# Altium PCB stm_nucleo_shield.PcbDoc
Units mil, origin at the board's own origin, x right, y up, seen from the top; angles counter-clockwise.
Board outline 4500 x 5500 mil, 2 copper layers (Top Layer, Bottom Layer); 14 components, 82 nets, 154 pads, 2 vias.
Unrouted connection lines stored in the file: 26.
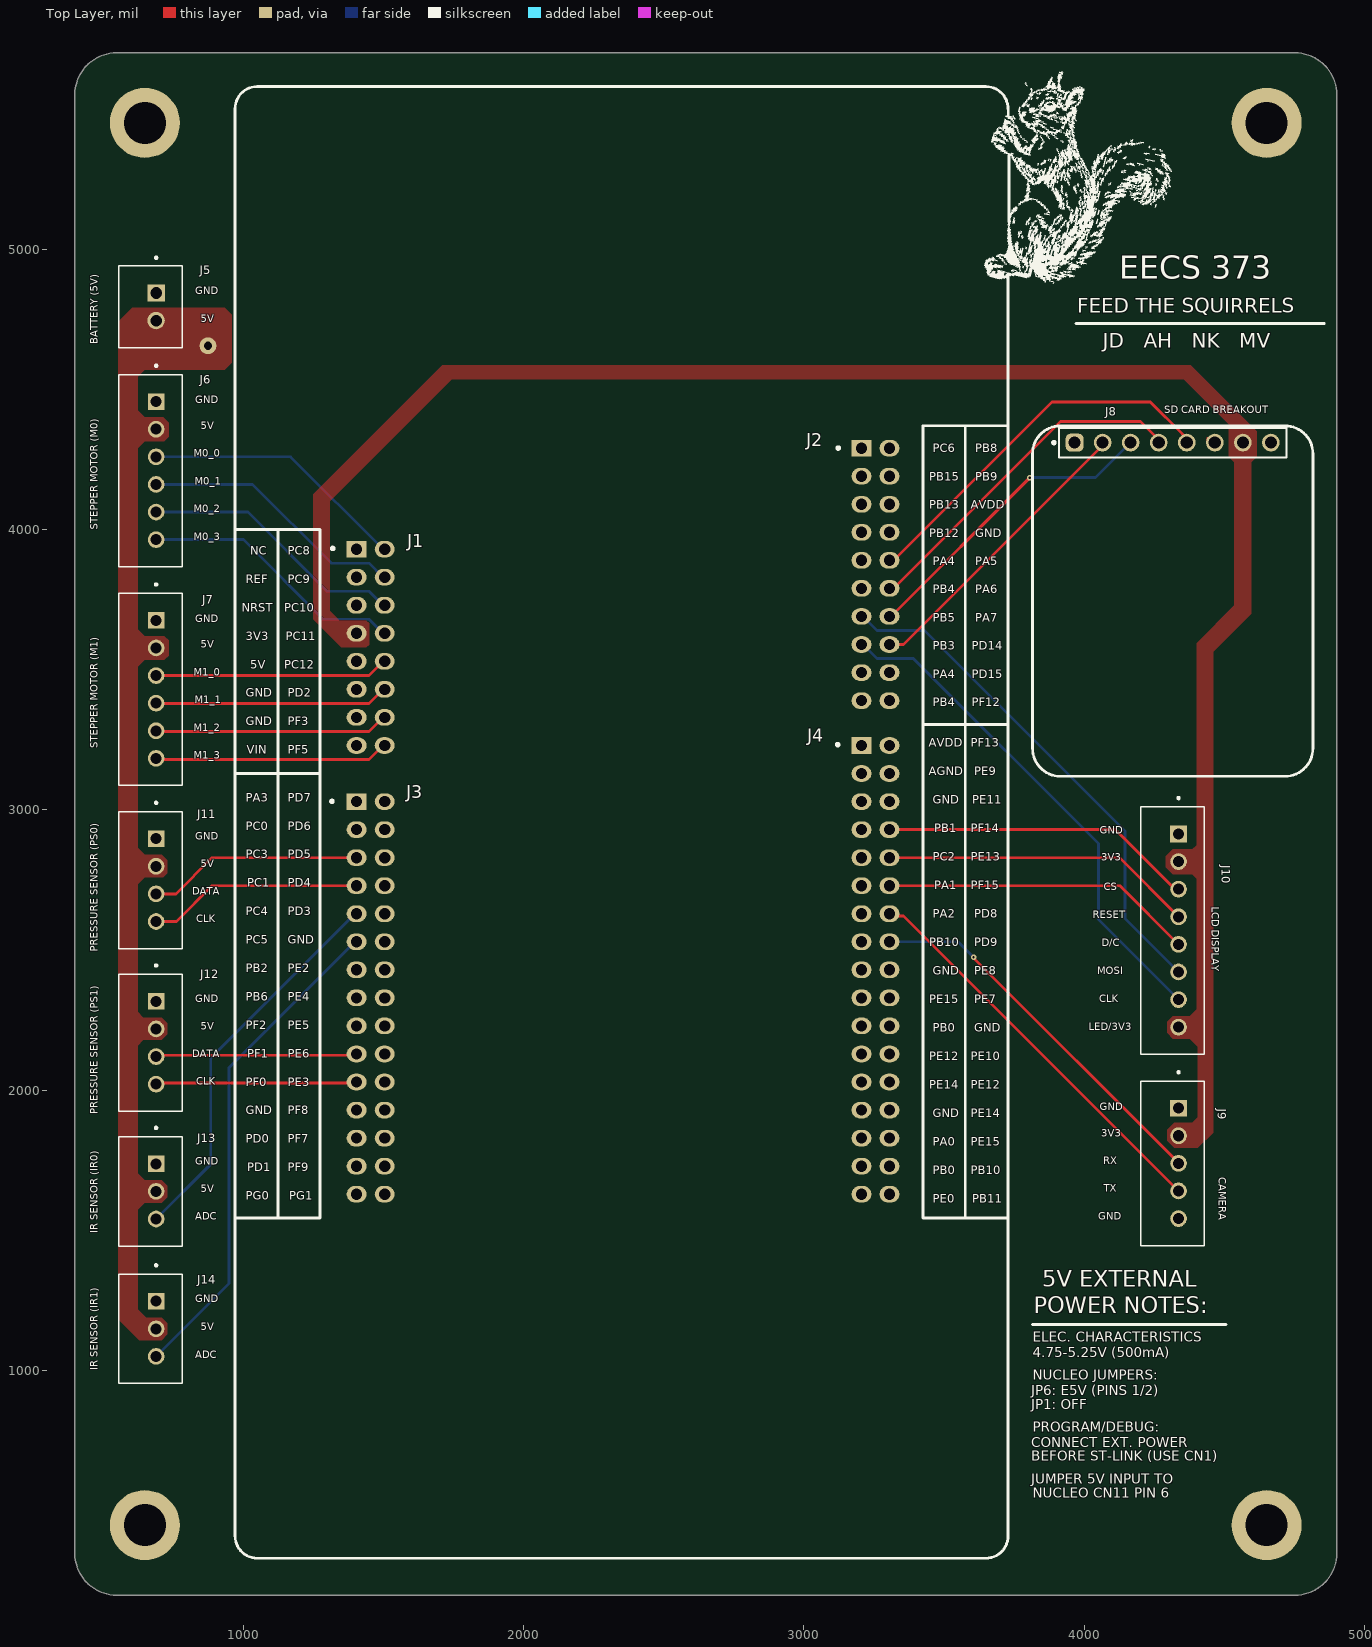
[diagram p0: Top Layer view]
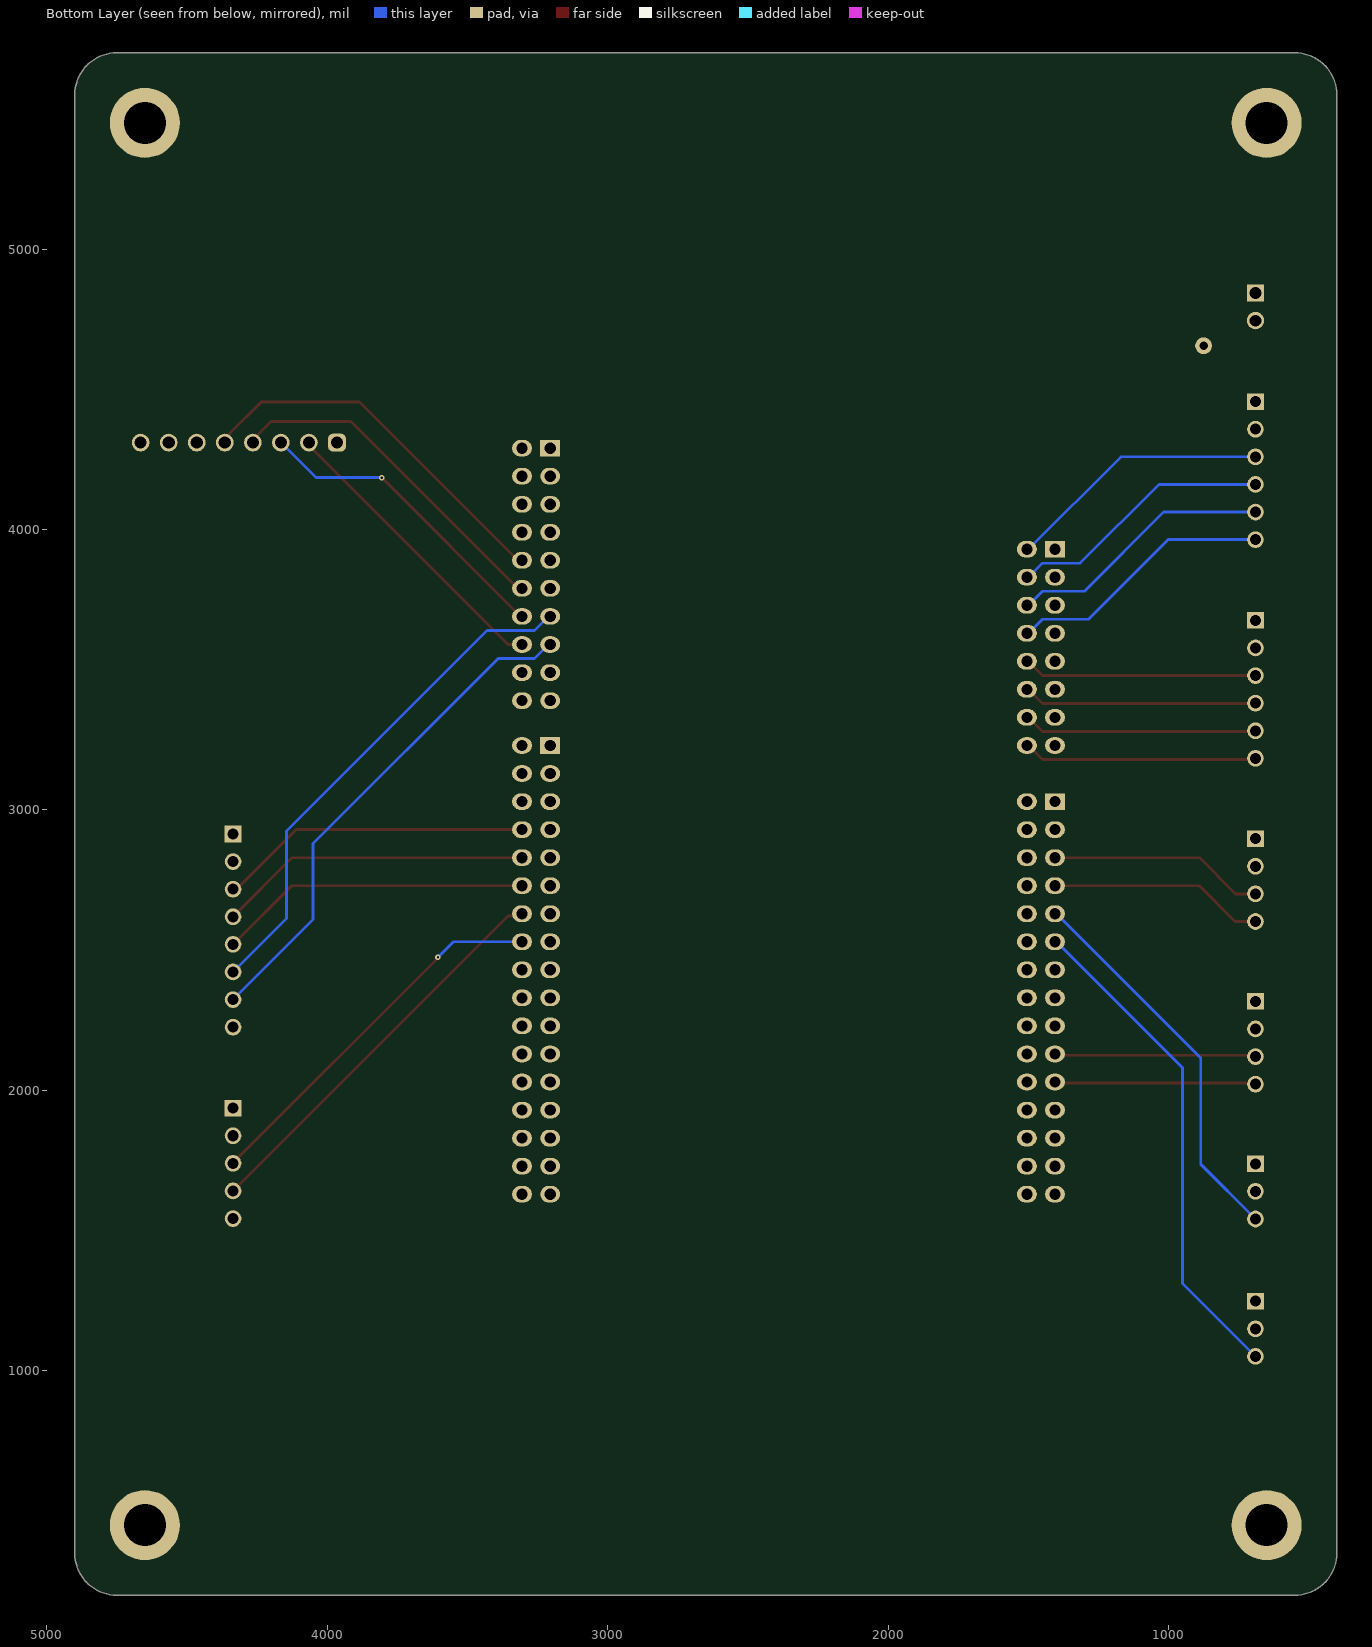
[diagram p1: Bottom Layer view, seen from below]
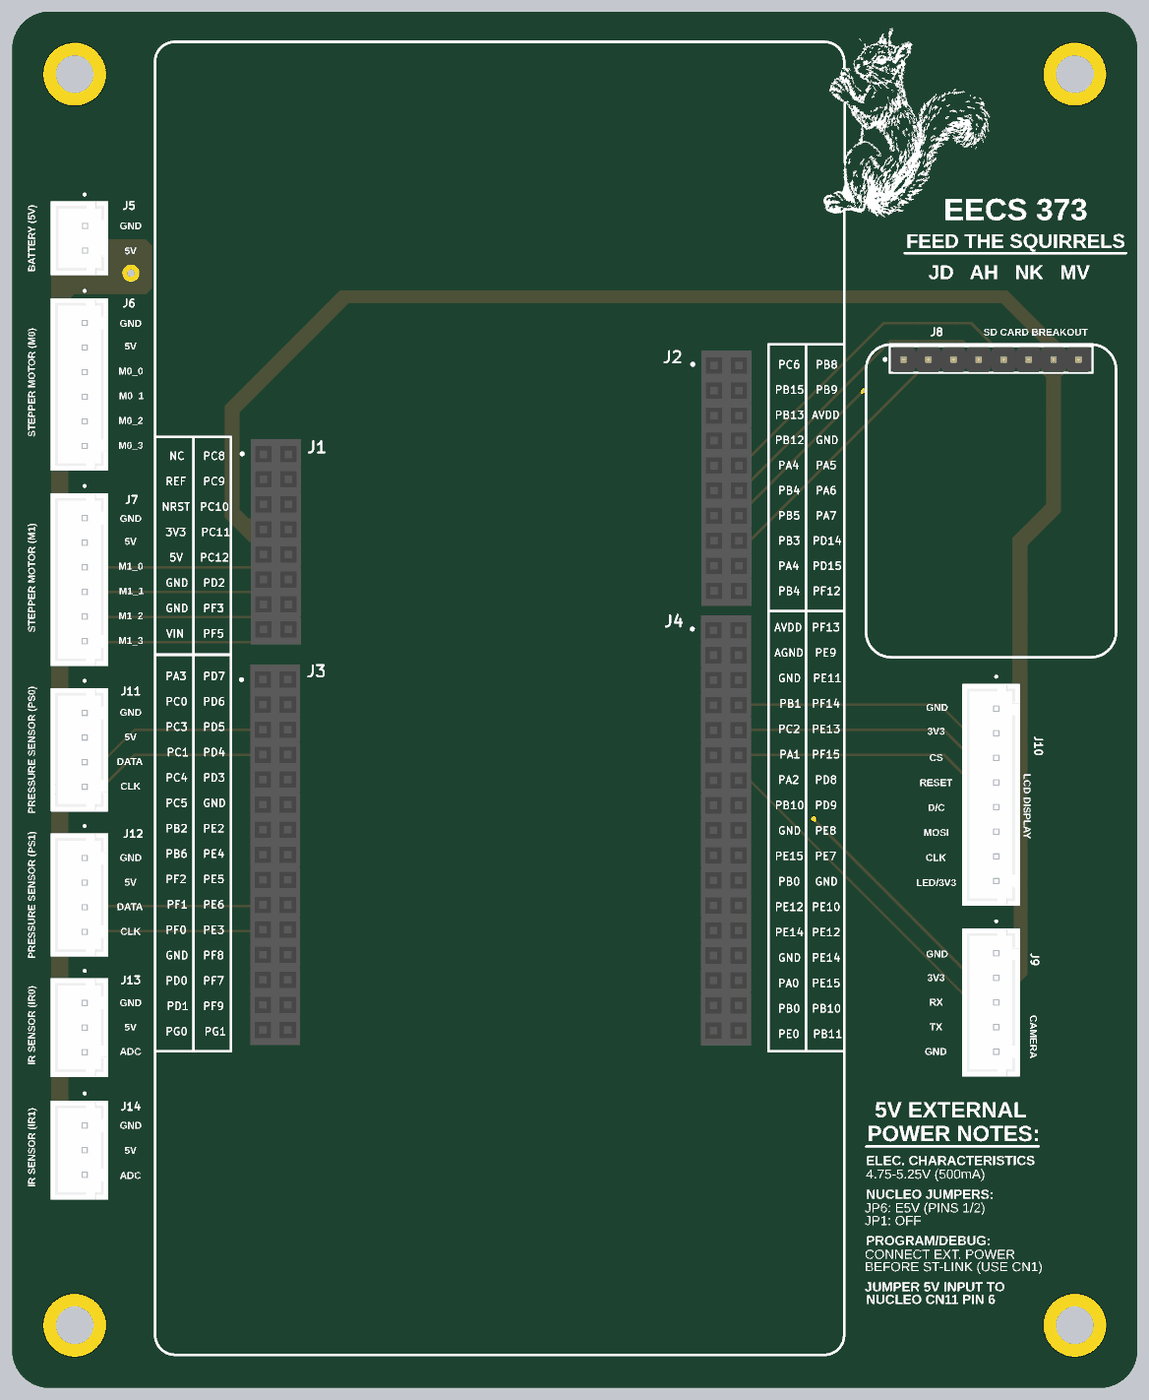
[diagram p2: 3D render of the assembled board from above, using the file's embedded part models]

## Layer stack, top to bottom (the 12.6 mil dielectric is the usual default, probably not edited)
Top Solder: solder mask 0.4, Solder Resist, Dk 3.5
Top Layer: signal copper 1.4
Dielectric 1: dielectric 12.6, FR-4, Dk 4.8
Bottom Layer: signal copper 1.4
Bottom Solder: solder mask 0.4, Solder Resist, Dk 3.5

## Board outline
400,350 ccw(c550,350) 550,200 4750,200 ccw(c4750,350) 4900,350 4900,5550 ccw(c4750,5550) 4750,5700 550,5700 ccw(c550,5550) 400,5550

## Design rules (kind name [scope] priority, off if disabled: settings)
Clearance [All] p1: gap=10 ignorepadtopadclearanceinfootprint=FALSE except(0: Arc-Hole Track-Hole SMDPad-Hole THPad-Hole Via-Hole Fill-Hole Poly-Hole Region-Hole Text-Hole)
PolygonConnect [All] p1: connectstyle=Direct reliefconductorwidth=10 reliefentries=4 polygonreliefangle="90 Angle" airgapwidth=10
RoutingVias [All] p1: holewidth=28 width=50 viastyle="Through Hole" minholewidth=28 minwidth=50 maxholewidth=28 maxwidth=50
SolderMaskExpansion [All] p1: expansion=4 istentingtop=FALSE
Width [All] p1: maxlimit=10 minlimit=10 preferedwidth=10
30 further rules are at their usual default settings.

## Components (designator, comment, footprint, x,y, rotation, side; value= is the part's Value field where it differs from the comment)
J1 "PPTC082LFBN-RC" CONN-STM32-16POS 1350,3982.56 r0 top locked
J2 "PPTC102LFBN-RC" CONN-STM32-20POS 3142,4345.56 r0 top locked
J3 "PPTC152LFBN-RC" CONN-STM32-30POS 1342.13,3090.59 r0 top locked
J4 "PPTC172LFBN-RC" CONN-STM32-34POS 3140.35,3293.04 r0 top locked
J5 "B2B-XH-A" JST_B2B-XH-A 669.33,4794.21 r90 top
J6 "B6B-XH-A" JST_B6B-XH-A 669.33,4210 r90 top
J7 "B6B-XH-A" JST_B6B-XH-A 669.33,3430 r90 top
J8 "61300811121" 61300811121 4315,4310 r0 top
J9 "B5B-XH-A" JST_B5B-XH-A 4315,1740 r90 top
J10 "B8B-XH-A" JST_B8B-XH-A 4315,2570 r90 top
J11 "B4B-XH-A" JST_B4B-XH-A 669.33,2750 r90 top
J12 "B4B-XH-A" JST_B4B-XH-A 669.33,2170 r90 top
J13 "B3B-XH-A" JST_B3B-XH-A 669.33,1640 r90 top
J14 "B3B-XH-A" JST_B3B-XH-A 669.33,1150 r90 top

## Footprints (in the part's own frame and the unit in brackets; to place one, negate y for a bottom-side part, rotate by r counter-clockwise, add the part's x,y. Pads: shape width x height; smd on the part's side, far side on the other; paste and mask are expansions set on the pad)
61300811121 [mm] "Pin Header, pitch 2.54 mm, THT, Vertical, single row, 8p"
  rrect50% 1.6x1.6 hole 1.1: 1(-8.89,0)
  round 1.6 hole 1.1: 2(-6.35,0) 3(-3.81,0) 4(-1.27,0) 5(1.27,0) 6(3.81,0) 7(6.35,0) 8(8.89,0)
  silkscreen extent -10.88,-1.35 10.31,1.35, body extent -10.16,-1.27 10.16,1.27, height 8.57
CONN-STM32-16POS [mm]
  rect 1.8x1.5 hole 1.02: 1(1.397,-1.335)
  oval 1.8x1.5 hole 1.02: 2(3.937,-1.335) 3(1.397,-3.875) 4(3.937,-3.875) 5(1.397,-6.415) 6(3.937,-6.415) 7(1.397,-8.955) 8(3.937,-8.955) 9(1.397,-11.495) 10(3.937,-11.495) 11(1.397,-14.035) 12(3.937,-14.035) 13(1.397,-16.575) 14(3.937,-16.575) 15(1.397,-19.115) 16(3.937,-19.115)
  silkscreen extent -0.89,-1.4 -0.64,-1.14, body extent 0.13,-20.62 5.21,0.21, height 8.51
CONN-STM32-20POS [mm]
  rect 1.8x1.5 hole 1.02: 1(1.6,-1.411)
  oval 1.8x1.5 hole 1.02: 2(4.14,-1.411) 3(1.6,-3.951) 4(4.14,-3.951) 5(1.6,-6.491) 6(4.14,-6.491) 7(1.6,-9.031) 8(4.14,-9.031) 9(1.6,-11.571) 10(4.14,-11.571) 11(1.6,-14.111) 12(4.14,-14.111) 13(1.6,-16.651) 14(4.14,-16.651) 15(1.6,-19.191) 16(4.14,-19.191) 17(1.6,-21.731) 18(4.14,-21.731) 19(1.6,-24.271) 20(4.14,-24.271)
  silkscreen extent -0.63,-1.52 -0.38,-1.27, body extent 0.38,-25.91 5.46,0, height 8.51
CONN-STM32-30POS [mm]
  rect 1.8x1.5 hole 1.02: 1(1.597,-1.539)
  oval 1.8x1.5 hole 1.02: 2(4.137,-1.539) 3(1.597,-4.079) 4(4.137,-4.079) 5(1.597,-6.619) 6(4.137,-6.619) 7(1.597,-9.159) 8(4.137,-9.159) 9(1.597,-11.699) 10(4.137,-11.699) 11(1.597,-14.239) 12(4.137,-14.239) 13(1.597,-16.779) 14(4.137,-16.779) 15(1.597,-19.319) 16(4.137,-19.319) 17(1.597,-21.859) 18(4.137,-21.859) 19(1.597,-24.399) 20(4.137,-24.399) 21(1.597,-26.939) 22(4.137,-26.939) 23(1.597,-29.479) 24(4.137,-29.479) 25(1.597,-32.019) 26(4.137,-32.019) 27(1.597,-34.559) 28(4.137,-34.559) 29(1.597,-37.099) 30(4.137,-37.099)
  silkscreen extent -0.76,-1.65 -0.51,-1.4, body extent 0.25,-38.61 5.33,0, height 8.51
CONN-STM32-34POS [mm]
  rect 1.8x1.5 hole 1.02: 1(1.642,-1.601)
  oval 1.8x1.5 hole 1.02: 2(4.182,-1.601) 3(1.642,-4.141) 4(4.182,-4.141) 5(1.642,-6.681) 6(4.182,-6.681) 7(1.642,-9.221) 8(4.182,-9.221) 9(1.642,-11.761) 10(4.182,-11.761) 11(1.642,-14.301) 12(4.182,-14.301) 13(1.642,-16.841) 14(4.182,-16.841) 15(1.642,-19.381) 16(4.182,-19.381) 17(1.642,-21.921) 18(4.182,-21.921) 19(1.642,-24.461) 20(4.182,-24.461) 21(1.642,-27.001) 22(4.182,-27.001) 23(1.642,-29.541) 24(4.182,-29.541) 25(1.642,-32.081) 26(4.182,-32.081) 27(1.642,-34.621) 28(4.182,-34.621) 29(1.642,-37.161) 30(4.182,-37.161) 31(1.642,-39.701) 32(4.182,-39.701) 33(1.642,-42.241) 34(4.182,-42.241)
  silkscreen extent -0.63,-1.65 -0.38,-1.4, body extent 0.38,-43.82 5.46,-0.13, height 8.51
JST_B2B-XH-A [mm]
  rect 1.575x1.575 / inner round 1.575 / far side rect 1.575x1.575 hole 1.05: 1(1.25,-0.525)
  round 1.575 hole 1.05: 2(-1.25,-0.525)
  silkscreen extent -3.7,-2.88 4.54,2.88, body extent -3.7,-2.92 3.7,2.83, height 7
JST_B3B-XH-A [mm]
  rect 1.508x1.508 / inner round 1.508 / far side rect 1.508x1.508 hole 1: 1(2.5,-0.525)
  round 1.508 hole 1: 2(0,-0.525) 3(-2.5,-0.525)
  silkscreen extent -4.95,-2.88 5.85,2.88, body extent -4.95,-2.88 4.95,2.88, height 7
JST_B4B-XH-A [mm]
  rect 1.508x1.508 / inner round 1.508 / far side rect 1.508x1.508 hole 1: 1(3.75,-0.525)
  round 1.508 hole 1: 2(1.25,-0.525) 3(-1.25,-0.525) 4(-3.75,-0.525)
  silkscreen extent -6.2,-2.88 7.1,2.88, body extent -6.2,-2.88 6.2,2.88, height 7
JST_B5B-XH-A [mm]
  rect 1.508x1.508 / inner round 1.508 / far side rect 1.508x1.508 hole 1: 1(5,-0.525)
  round 1.508 hole 1: 2(2.5,-0.525) 3(0,-0.525) 4(-2.5,-0.525) 5(-5,-0.525)
  silkscreen extent -7.45,-2.88 8.35,2.88, body extent -7.45,-2.88 7.45,2.88, height 7
JST_B6B-XH-A [mm]
  rect 1.508x1.508 / inner round 1.508 / far side rect 1.508x1.508 hole 1: 1(6.25,-0.525)
  round 1.508 hole 1: 2(3.75,-0.525) 3(1.25,-0.525) 4(-1.25,-0.525) 5(-3.75,-0.525) 6(-6.25,-0.525)
  silkscreen extent -8.7,-2.88 9.6,2.88, body extent -8.7,-2.88 8.7,2.88, height 7
JST_B8B-XH-A [mm]
  rect 1.508x1.508 / inner round 1.508 / far side rect 1.508x1.508 hole 1: 1(8.75,-0.525)
  round 1.508 hole 1: 2(6.25,-0.525) 3(3.75,-0.525) 4(1.25,-0.525) 5(-1.25,-0.525) 6(-3.75,-0.525) 7(-6.25,-0.525) 8(-8.75,-0.525)
  silkscreen extent -11.2,-2.88 12.1,2.88, body extent -11.2,-2.88 11.2,2.88, height 7

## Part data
J1: library part CONN-STM32-16POS, "16 Position Header Connector 0.100\" (2.54mm) Through Hole Tin"
J2: library part CONN-STM32-20POS, "20 Position Header Connector 0.100\" (2.54mm) Through Hole Tin"
J3: library part CONN-STM32-30POS, "30 Position Header Connector 0.100\" (2.54mm) Through Hole Tin"
J4: library part CONN-STM32-34POS, "34 Position Header Connector 0.100\" (2.54mm) Through Hole Tin"
J5: library part CONN-2POS-0001, Package=43650-0215
J6 J7: library part CONN-6POS-0001, Package=43650-0215
J8: library part CONN-8POS-0002, Package=43650-0215
J9: library part CONN-5POS-0001, Package=43650-0215
J10: library part CONN-8POS-0001, Package=43650-0215
J11 J12: library part CONN-4POS-0001, Package=43650-0215
J13 J14: library part CONN-3POS-0001, Package=43650-0215

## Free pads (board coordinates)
  round 60 hole 30: 2(875,4655)
  round 250 hole 150: ""(650,450) ""(650,5450) ""(4650,450) ""(4650,5450)

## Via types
v1: diameter 20, hole 8, Top Layer to Bottom Layer, 2 vias

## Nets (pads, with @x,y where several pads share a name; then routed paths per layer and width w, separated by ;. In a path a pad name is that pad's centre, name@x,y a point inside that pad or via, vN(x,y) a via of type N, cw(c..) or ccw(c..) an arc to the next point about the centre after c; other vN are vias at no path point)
3V3: J1.7 J8.7 J9.2 J10.2 J10.8
+5V: J1.9
AGND: J4.3
AVDD: J4.1
GND: J1.11 J1.13 J2.8 J3.12 J3.23 J4.5 J4.17 J4.22 J4.27 J5.1 J6.1 J7.1 J8.6 J9.1 J9.5 J10.1 J11.1 J12.1 J13.1 J14.1
IOREF: J1.3
NRST: J1.5
PA0: J4.29
PA1: J4.11
PA2: J4.13
PA3: J3.1
PA4: J2.9
PA5: J2.10 J8.5 | length 1362.9
  Top Layer w10: J2.10 3320,3890 3885,4455 4235,4455 4349.62,4340.38 4349.62,4339.72 J8.5@4365,4324.34 ; 4440,4310 4440,4324.34
PA6: J2.12 J8.4 | length 1240.5
  Top Layer w10: J2.12 3320,3790 3915,4385 4200,4385 J8.4@4270,4315
PA7: J2.14 J8.3 | length 1127.1
  Top Layer w10: J2.14 3310.45,3690 3805,4184.55 v1(3805,4185) ; J8.3@4160,4310 J8.3@4160,4320
  Bottom Layer w10: v1(3805,4185) 4040,4185 J8.3
PB0: J4.21 J4.31
PB1: J4.7
PB2: J3.13
PB3: J2.15 J10.7 | length 1825.3
  Top Layer w10: J2.15@3199.09,3590 J2.15 J2.15@3210.91,3590
  Bottom Layer w10: J2.15 3210.91,3590 3260.91,3540 3390,3540 4050,2880 4050,2609.61 J10.7
PB4: J2.11
PB5: J2.13 J10.6 | length 1844.4
  Top Layer w10: J2.13@3199.09,3690 J2.13
  Bottom Layer w10: J2.13 3210.91,3690 3260.91,3640 3430,3640 4145,2925 4145,2613.03 J10.6
PB6: J3.15
PB8: J2.2
PB9: J2.4
PB10: J4.15 J4.32
PB11: J4.34
PB12: J2.7
PB13: J2.5
PB15: J2.3
PC0: J3.3
PC1: J3.7 J11.4 | length 767.9
  Top Layer w10: J11.4 762.36,2602.36 890,2730 J3.7
PC2: J4.9
PC3: J3.5 J11.3 | length 768.5
  Top Layer w10: J11.3 760.79,2700.79 890,2830 J3.5
PC4: J3.9 J13.3 | length 1388
  Bottom Layer w10: J13.3 885,1736.57 885,2115.91 1399.09,2630 J3.9
PC5: J3.11 J14.3 | length 1778
  Bottom Layer w10: J14.3 950,1311.57 950,2080.91 1399.09,2530 J3.11
PC6: J2.1
PC8: J1.2 J6.3 | length 951.4
  Bottom Layer w10: J6.3 1169.88,4259.21 1499.09,3930 J1.2
PC9: J1.4 J6.4 | length 952
  Bottom Layer w10: J6.4 1034.21,4160.79 1315,3880 1449.09,3880 1499.09,3830 J1.4
PC10: J1.6 J6.5 | length 952.7
  Bottom Layer w10: J6.5 1017.64,4062.36 1300,3780 1449.09,3780 1499.09,3730 J1.6
PC11: J1.8 J6.6 | length 953.3
  Bottom Layer w10: J6.6 1001.06,3963.94 1285,3680 1449.09,3680 1499.09,3630 J1.8
PC12: J1.10 J7.3 | length 835.7
  Top Layer w10: J7.3@690,3480 1449.09,3480 1499.09,3530 J1.10
PD0: J3.25
PD1: J3.27
PD2: J1.12 J7.4 | length 835.7
  Top Layer w10: J7.4@690,3380 1449.09,3380 1499.09,3430 J1.12
PD3: J3.10
PD4: J3.8
PD5: J3.6
PD6: J3.4
PD7: J3.2
PD8: J4.14 J9.4 | length 1440.1
  Top Layer w10: J4.14 3313.19,2621.81 3355.43,2621.81 J9.4
PD9: J4.16 J9.3 | length 1366.9
  Top Layer w10: J4.16 J4.16@3309.61,2525.39 ; v1(3605,2475) 3605,2472.83 4335.67,1742.17 J9.3
  Bottom Layer w10: J4.16 3550,2530 v1(3605,2475)
PD14: J2.16 J8.2 | length 1064.1
  Top Layer w10: J2.16 3355,3590 J8.2@4065,4300 ; 4190,4300 4190,4310
PD15: J2.18
PE0: J4.33
PE2: J3.14
PE3: J3.22
PE4: J3.16
PE5: J3.18
PE6: J3.20
PE9: J4.4
PE10: J4.24
PE11: J4.6
PE12: J4.23 J4.26
PE13: J4.10 J10.4 | length 1118
  Top Layer w10: J4.10 4124.88,2830 J10.4
PE14: J4.25 J4.28
PE15: J4.19 J4.30
PF0: J3.21 J12.4 | length 718.2
  Top Layer w10: J12.4 693.82,2026.18 1401.18,2026.18 J3.21
PF1: J3.19 J12.3 | length 718.8
  Top Layer w10: J12.3 694.61,2125.39 1400.39,2125.39 J3.19
PF2: J3.17
PF3: J1.14 J7.5 | length 835.7
  Top Layer w10: J7.5@690,3280 1449.09,3280 1499.09,3330 J1.14
PF5: J1.16 J7.6 | length 835.7
  Top Layer w10: J7.6@690,3180 1449.09,3180 1499.09,3230 J1.16
PF7: J3.26
PF8: J3.24
PF9: J3.28
PF12: J2.20
PF13: J4.2
PF14: J4.8 J10.3 | length 1118.6
  Top Layer w10: J4.8 4110,2930 4322.36,2717.64 J10.3
PF15: J4.12 J10.5 | length 1130.6
  Top Layer w10: J4.12@3314.39,2720.61 J4.12 4126.46,2730 J10.5
PG0: J3.29
PG1: J3.30
"VBAT (5V)": J5.2 J6.2 J7.2 J11.2 J12.2 J13.2 J14.2 pad.2
VIN: J1.15
pads on no net: J1.1 J2.6 J2.17 J2.19 J4.18 J4.20 J8.1 J8.8

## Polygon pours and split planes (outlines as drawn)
"VBAT (5V)" on Top Layer "VBAT_(5V)_L01_P001" (solid, pour order 1): 730,1130 710,1110 630,1110 555,1185 555,4740 605,4790 935,4790 960,4765 960,4595 935,4570 650,4570 625,4545 625,4425 650,4400 715,4400 735,4380 735,4330 720,4315 650,4315 625,4290 625,3645 650,3620 720,3620 735,3605 735,3550 720,3535 650,3535 625,3510 625,2865 650,2840 710,2840 730,2820 730,2775 715,2760 650,2760 625,2735 625,2280 645,2260 710,2260 730,2240 730,2200 710,2180 645,2180 625,2160 625,1705 650,1680 710,1680 730,1660 730,1620 710,1600 650,1600 625,1575 625,1220 655,1190 710,1190 730,1170
3V3 on Top Layer "3V3_L01_P000" (solid, pour order 0): 4460,1975 4460,1850 4405,1795 4320,1795 4295,1820 4295,1860 4320,1885 4385,1885 4405,1905 4405,2010 4405,2155 4375,2185 4315,2185 4295,2205 4295,2245 4315,2265 4375,2265 4400,2290 4400,2395 4400,2755 4385,2770 4315,2770 4290,2795 4290,2835 4315,2860 4385,2860 4400,2875 4400,2985 4400,3595 4535,3730 4535,4240 4515,4260 4515,4375 4355,4535 1745,4535 1310,4100 1310,3710 1345,3675 1440,3675 1450,3665 1450,3590 1440,3580 1350,3580 1250,3680 1250,4125 1710,4585 4380,4585 4615,4350 4615,4260 4595,4240 4595,3700 4460,3565

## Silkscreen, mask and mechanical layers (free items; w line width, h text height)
Top Overlay:
  drawing of 178 lines, arcs and shapes, not listed
  text "EECS 373" at 4125,4866.68 h140
  text "GND" at 830.18,4830.54 h45
  text "FEED THE SQUIRRELS" at 3975,4755.91 h90
  text "5V" at 849.19,4730.54 h45
  text "BATTERY (5V)" at 491.51,4660 h45 r90
  text "JD   AH   NK   MV" at 4065,4631.08 h90
  text "GND" at 830.18,4440.54 h45
  text "SD CARD BREAKOUT" at 4285,4405.54 h45
  text "5V" at 849.19,4349.08 h45
  text "PC6" at 3460,4275 h30
  text "PB8" at 3610,4275 h30
  text "M0_0" at 825,4250.05 h45
  text "PB15" at 3447.5,4174.44 h30
  text "PB9" at 3610,4174.44 h30
  text "M0_1" at 827.29,4151.01 h45
  text "PB13" at 3447.5,4073.89 h30
  text "AVDD" at 3595,4073.89 h30
  text "M0_2" at 825.02,4051.98 h45
  text "STEPPER MOTOR (M0)" at 491.53,4000 h45 r90
  text "PB12" at 3447.5,3973.33 h30
  text "GND" at 3610,3973.33 h30
  text "M0_3" at 824.88,3952.95 h45
  text "NC" at 1025,3910 h30
  text "PC8" at 1160,3910 h30
  text "PA4" at 3460,3872.78 h30
  text "PA5" at 3610,3872.78 h30
  text "REF" at 1010,3808.57 h30
  text "PC9" at 1160,3808.57 h30
  text "PB4" at 3460,3772.22 h30
  text "PA6" at 3610,3772.22 h30
  text "NRST" at 995.01,3707.14 h30
  text "PC10" at 1147.5,3707.14 h30
  text "PB5" at 3460,3671.67 h30
  text "PA7" at 3610,3671.67 h30
  text "GND" at 830.18,3660.54 h45
  text "3V3" at 1010,3605.71 h30
  text "PC11" at 1152.5,3605.71 h30
  text "PB3" at 3460,3571.11 h30
  text "PD14" at 3597.5,3571.11 h30
  text "5V" at 849.19,3569.08 h45
  text "5V" at 1025,3504.29 h30
  text "PC12" at 1147.5,3504.29 h30
  text "PA4" at 3460,3470.56 h30
  text "PD15" at 3597.5,3470.56 h30
  text "M1_0" at 825,3470.05 h45
  text "GND" at 1010,3402.86 h30
  text "PD2" at 1160,3402.86 h30
  text "M1_1" at 827.29,3371.01 h45
  text "PB4" at 3460,3370 h30
  text "PF12" at 3597.5,3370 h30
  text "GND" at 1010,3301.43 h30
  text "PF3" at 1160,3301.43 h30
  text "M1_2" at 825.02,3271.98 h45
  text "AVDD" at 3445,3225 h30
  text "PF13" at 3595,3225 h30
  text "STEPPER MOTOR (M1)" at 491.53,3220 h45 r90
  text "VIN" at 1012.5,3200 h30
  text "PF5" at 1160,3200 h30
  text "M1_3" at 824.88,3172.95 h45
  text "AGND" at 3445,3123.44 h30
  text "PE9" at 3607.5,3123.44 h30
  text "PA3" at 1010,3030 h30
  text "PD7" at 1160,3030 h30
  text "GND" at 3460,3021.88 h30
  text "PE11" at 3600,3021.88 h30
  text "PC0" at 1010,2928.57 h30
  text "PD6" at 1160,2928.57 h30
  text "PB1" at 3464.99,2920.31 h30
  text "PF14" at 3595,2920.31 h30
  text "GND" at 4055,2905.54 h45
  text "GND" at 830.18,2885.54 h45
  text "PC3" at 1010,2827.14 h30
  text "PD5" at 1160,2827.14 h30
  text "PC2" at 3460,2818.75 h30
  text "PE13" at 3595,2818.75 h30
  text "3V3" at 4060,2810.54 h45
  text "5V" at 849.19,2787.18 h45
  text "PC1" at 1015,2725.71 h30
  text "PD4" at 1160,2725.71 h30
  text "PA1" at 3464.99,2717.19 h30
  text "PF15" at 3595,2717.19 h30
  text "CS" at 4068.23,2705.51 h45
  text "DATA" at 818.61,2689.36 h45
  text "LCD DISPLAY" at 4445.54,2655 h45 r270
  text "PC4" at 1010,2624.28 h30
  text "PD3" at 1160,2624.28 h30
  text "PA2" at 3460,2615.62 h30
  text "PD8" at 3607.5,2615.62 h30
  text "RESET" at 4029.04,2605.49 h45
  text "CLK" at 832.57,2590.5 h45
  text "PC5" at 1010,2522.86 h30
  text "GND" at 1160,2522.86 h30
  text "PB10" at 3447.5,2514.06 h30
  text "PD9" at 3607.5,2514.06 h30
  text "D/C" at 4062.09,2505.51 h45
  text "PRESSURE SENSOR (PS0)" at 491.53,2495 h45 r90
  text "PB2" at 1010,2421.43 h30
  text "PE2" at 1160,2421.43 h30
  text "GND" at 3460,2412.5 h30
  text "PE8" at 3607.5,2412.5 h30
  text "MOSI" at 4045.53,2405.49 h45
  text "PB6" at 1010,2320 h30
  text "PE4" at 1160,2320 h30
  text "PE15" at 3447.5,2310.94 h30
  text "PE7" at 3607.5,2310.94 h30
  text "GND" at 830.18,2305.54 h45
  text "CLK" at 4053.88,2305.52 h45
  text "PF2" at 1010,2218.57 h30
  text "PE5" at 1160,2218.57 h30
  text "PB0" at 3460,2209.38 h30
  text "GND" at 3607.5,2209.38 h30
  text "5V" at 849.19,2207.18 h45
  text "LED/3V3" at 4015,2205.54 h45
  text "PF1" at 1015,2117.14 h30
  text "PE6" at 1160,2117.14 h30
  text "DATA" at 818.61,2109.36 h45
  text "PE12" at 3447.5,2107.81 h30
  text "PE10" at 3595,2107.81 h30
  text "PF0" at 1010,2015.71 h30
  text "PE3" at 1160,2015.71 h30
  text "CLK" at 832.57,2010.5 h45
  text "PE14" at 3447.5,2006.25 h30
  text "PE12" at 3595,2006.25 h30
  text "GND" at 4055,1920.54 h45
  text "PRESSURE SENSOR (PS1)" at 491.53,1915 h45 r90
  text "GND" at 1010,1914.29 h30
  text "PF8" at 1160,1914.29 h30
  text "GND" at 3460,1904.69 h30
  text "PE14" at 3595,1904.69 h30
  text "3V3" at 4060,1825.54 h45
  text "PD0" at 1010,1812.86 h30
  text "PF7" at 1160,1812.86 h30
  text "PA0" at 3460,1803.12 h30
  text "PE15" at 3595,1803.12 h30
  text "RX" at 4067.79,1727.85 h45
  text "GND" at 830.18,1725.54 h45
  text "PD1" at 1015,1711.43 h30
  text "PF9" at 1160,1711.43 h30
  text "PB0" at 3460,1701.56 h30
  text "PB10" at 3595,1701.56 h30
  text "CAMERA" at 4470.5,1690 h45 r270
  text "TX" at 4069,1629.55 h45
  text "5V" at 849.19,1628.27 h45
  text "PG0" at 1010,1610 h30
  text "PG1" at 1165,1610 h30
  text "PE0" at 3460,1600 h30
  text "PB11" at 3600,1600 h30
  text "GND" at 4050,1530.54 h45
  text "ADC" at 830.39,1530.5 h45
  text "IR SENSOR (IR0)" at 491.53,1490 h45 r90
  text "5V EXTERNAL" at 3850,1281.2 h100
  text "GND" at 830.18,1235.54 h45
  text "POWER NOTES:" at 3820,1186.2 h100
  text "5V" at 849.19,1135.77 h45
  text "ELEC. CHARACTERISTICS" at 3815,1090.72 h60
  text "4.75-5.25V (500mA)" at 3815,1036.32 h60
  text "ADC" at 830.39,1035.5 h45
  text "IR SENSOR (IR1)" at 491.53,1002.01 h45 r90
  text "NUCLEO JUMPERS:" at 3815,955.72 h60
  text "JP6: E5V (PINS 1/2)" at 3809.89,901.32 h60
  text "JP1: OFF" at 3809.89,850.67 h60
  text "PROGRAM/DEBUG:" at 3815,770.72 h60
  text "CONNECT EXT. POWER" at 3810,715.67 h60
  text "BEFORE ST-LINK (USE CN1)" at 3810,666.32 h60
  text "JUMPER 5V INPUT TO" at 3810,585.72 h60
  text "NUCLEO CN11 PIN 6" at 3815,535.72 h60
Mechanical 1:
  the board outline again, w10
